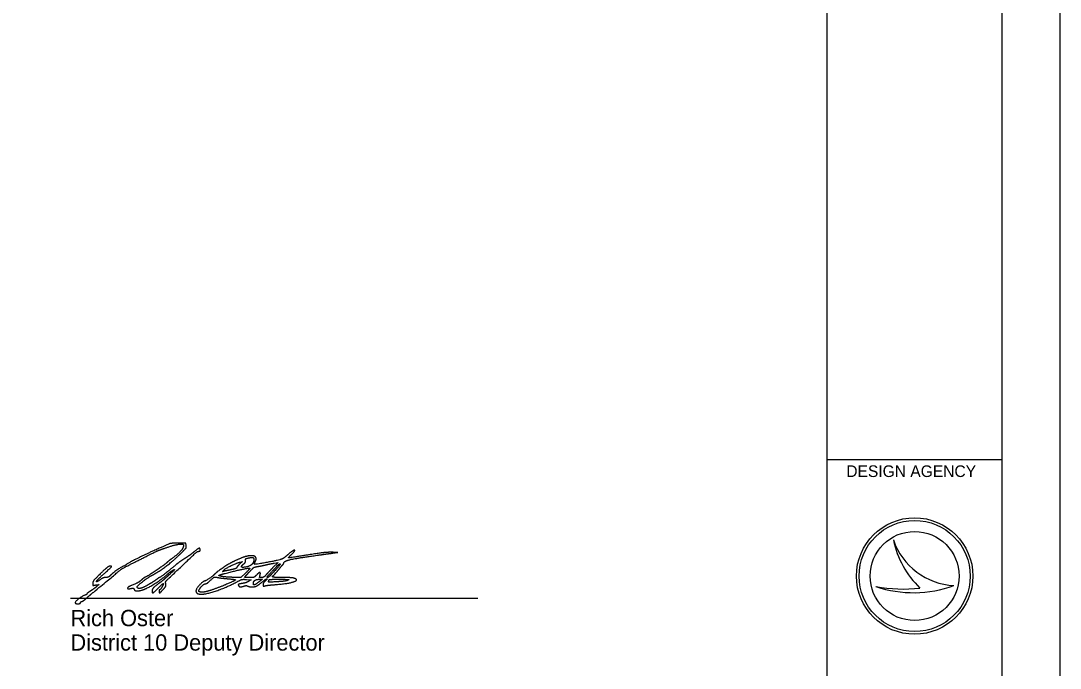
# Model space of a CAD drawing. Extents: x -22 to 431, y -18 to 160.
# Drawn here: x 25.07 to 34, y 2.71 to 8.27 of the extents above; entities that cross this region are included whole.
import ezdxf

# ---------------------------------------------------------------- set-up
doc = ezdxf.new("R2010")
doc.units = 0
for name, color, linetype in [('GM_X_County', 7, 'Continuous'), ('GM_X_Minor_Lake', 7, 'Continuous'), ('GM_X_Section', 7, 'Continuous'), ('GM_X_Township', 7, 'Continuous')]:
    doc.layers.add(name, color=color, linetype=linetype)

msp = doc.modelspace()

# ---------------------------------------------------------------- linework, layer by layer
at = {"layer": 'GM_X_County'}
msp.add_lwpolyline([(0, 0), (34, 0), (34, 22), (0, 22)], close=True, dxfattribs=at)
at = {"layer": 'GM_X_Minor_Lake'}
msp.add_line((25.5414, 3.2723), (25.5414, 3.2723), dxfattribs=at)
for points in [[(26.4927, 3.7616), (26.4902, 3.7834), (26.4302, 3.7827)], [(27.7539, 3.6969), (27.7952, 3.7027), (27.7575, 3.7037)], [(26.9553, 3.6188), (26.9777, 3.6241), (26.9533, 3.6018)], [(27.2502, 3.6103), (27.2828, 3.615), (27.239, 3.5717)], [(27.0037, 3.5251), (26.9645, 3.4871), (26.9111, 3.4881)], [(27.0364, 3.4871), (26.9955, 3.4871), (27.0347, 3.5317)], [(25.7195, 3.4229), (25.7477, 3.4279), (25.7252, 3.409)], [(27.013, 3.4707), (27.0522, 3.4684), (27.0308, 3.4544)], [(27.124, 3.4721), (27.1491, 3.4721), (27.1196, 3.4498)]]:
    msp.add_lwpolyline(points, dxfattribs=at)
for points in [[(26.4302, 3.7827), (26.3677, 3.782), (26.3413, 3.7738), (26.2052, 3.7126)], [(26.3327, 3.7466), (26.3967, 3.7685), (26.4714, 3.7785), (26.4714, 3.7652)], [(26.4714, 3.7652), (26.4714, 3.7413), (26.4264, 3.6899), (26.3672, 3.6464)], [(26.4326, 3.6791), (26.4866, 3.7314), (26.4948, 3.7427), (26.4927, 3.7616)], [(26.2052, 3.7126), (26.125, 3.6766), (25.9891, 3.607), (25.9758, 3.5952)], [(26.1227, 3.6544), (26.2348, 3.7107), (26.2605, 3.722), (26.3327, 3.7466)], [(26.2093, 3.5112), (26.263, 3.5396), (26.3777, 3.6258), (26.4326, 3.6791)], [(26.3476, 3.483), (26.569, 3.6926), (26.5909, 3.7121), (26.6045, 3.7121)], [(26.5646, 3.7097), (26.5484, 3.696), (26.5115, 3.6695), (26.4827, 3.6509)], [(26.6139, 3.7234), (26.6139, 3.7414), (26.5963, 3.7365), (26.5646, 3.7097)], [(26.6045, 3.7121), (26.6097, 3.7121), (26.6139, 3.7172), (26.6139, 3.7234)], [(27.0565, 3.6746), (27.029, 3.6746), (26.9672, 3.6555), (26.9117, 3.6298)], [(27.0866, 3.6224), (27.0994, 3.6463), (27.0831, 3.6746), (27.0565, 3.6746)], [(27.3651, 3.6813), (27.3459, 3.6644), (27.3234, 3.648), (27.3152, 3.645)], [(27.3339, 3.6143), (27.3339, 3.6287), (27.4565, 3.6559), (27.6272, 3.6793)], [(27.4007, 3.6878), (27.4375, 3.7246), (27.408, 3.7193), (27.3651, 3.6813)], [(27.4974, 3.6738), (27.3771, 3.6543), (27.3685, 3.6555), (27.4007, 3.6878)], [(27.7575, 3.7037), (27.7131, 3.7048), (27.6291, 3.6952), (27.4974, 3.6738)], [(27.6272, 3.6793), (27.6742, 3.6858), (27.7312, 3.6937), (27.7539, 3.6969)], [(25.7139, 3.3742), (25.9385, 3.5602), (25.9481, 3.5667), (26.1227, 3.6544)], [(25.8343, 3.5833), (25.8262, 3.582), (25.7908, 3.5526), (25.7555, 3.518)], [(25.8245, 3.5517), (25.8523, 3.5759), (25.8556, 3.5868), (25.8343, 3.5833)], [(25.9567, 3.5846), (25.948, 3.5846), (25.8583, 3.5208), (25.8392, 3.501)], [(25.9758, 3.5952), (25.9693, 3.5894), (25.9607, 3.5846), (25.9567, 3.5846)], [(26.3269, 3.6133), (26.3121, 3.5984), (26.1454, 3.4871), (26.138, 3.4871)], [(26.4077, 3.5977), (26.363, 3.5593), (26.2703, 3.4871), (26.2656, 3.4871)], [(26.3672, 3.6464), (26.3523, 3.6354), (26.3342, 3.6205), (26.3269, 3.6133)], [(26.4827, 3.6509), (26.4538, 3.6323), (26.42, 3.6083), (26.4077, 3.5977)], [(26.9117, 3.6298), (26.8697, 3.6103), (26.7612, 3.538), (26.7355, 3.5123)], [(26.8164, 3.5494), (26.8308, 3.5643), (26.9259, 3.6118), (26.9553, 3.6188)], [(26.9289, 3.572), (26.9289, 3.5679), (26.9095, 3.5603), (26.8858, 3.5552)], [(26.9533, 3.6018), (26.9399, 3.5896), (26.9289, 3.5762), (26.9289, 3.572)], [(27.0583, 3.6002), (27.0419, 3.5829), (26.9609, 3.5695), (26.9706, 3.5857)], [(26.9706, 3.5857), (26.974, 3.5913), (26.9829, 3.6003), (26.9903, 3.6057)], [(26.9903, 3.6057), (26.9978, 3.6111), (27.0039, 3.6233), (27.0039, 3.6329)], [(27.0039, 3.6329), (27.0039, 3.6463), (27.0092, 3.6513), (27.0273, 3.655)], [(27.0273, 3.655), (27.0402, 3.6575), (27.0554, 3.6596), (27.0611, 3.6596)], [(27.0347, 3.5317), (27.0671, 3.5685), (27.0793, 3.5771), (27.1046, 3.5811)], [(27.0611, 3.6596), (27.0761, 3.6596), (27.0741, 3.6169), (27.0583, 3.6002)], [(27.0818, 3.6017), (27.0796, 3.604), (27.0817, 3.6133), (27.0866, 3.6224)], [(27.3152, 3.645), (27.2878, 3.6349), (27.0861, 3.5975), (27.0818, 3.6017)], [(27.1046, 3.5811), (27.1214, 3.5837), (27.1537, 3.5903), (27.1764, 3.5957)], [(27.1764, 3.5957), (27.1991, 3.6012), (27.2323, 3.6077), (27.2502, 3.6103)], [(27.239, 3.5717), (27.2149, 3.5478), (27.1876, 3.519), (27.1783, 3.5077)], [(27.1918, 3.4871), (27.1839, 3.4871), (27.2053, 3.5123), (27.2763, 3.5866)], [(27.3009, 3.6052), (27.3044, 3.6017), (27.2806, 3.5727), (27.2279, 3.5163)], [(27.2763, 3.5866), (27.2879, 3.5987), (27.299, 3.6071), (27.3009, 3.6052)], [(27.2814, 3.5471), (27.2999, 3.5698), (27.3193, 3.5928), (27.3245, 3.5983)], [(27.3245, 3.5983), (27.3297, 3.6037), (27.3339, 3.6109), (27.3339, 3.6143)], [(25.7555, 3.518), (25.7091, 3.4726), (25.6914, 3.45), (25.6914, 3.4366)], [(25.7245, 3.4515), (25.7208, 3.4552), (25.7677, 3.5022), (25.8245, 3.5517)], [(25.8031, 3.4871), (25.7901, 3.4871), (25.7693, 3.4787), (25.7545, 3.4673)], [(25.8392, 3.501), (25.8319, 3.4934), (25.8156, 3.4871), (25.8031, 3.4871)], [(26.0739, 3.4072), (26.0739, 3.4167), (26.1697, 3.4903), (26.2093, 3.5112)], [(26.138, 3.4871), (26.1354, 3.4871), (26.1242, 3.4787), (26.113, 3.4684)], [(26.1272, 3.3834), (26.1642, 3.3962), (26.2908, 3.4772), (26.3364, 3.5174)], [(26.2656, 3.4871), (26.2629, 3.4871), (26.2567, 3.4837), (26.2517, 3.4795)], [(26.3523, 3.5139), (26.3377, 3.5012), (26.3201, 3.4854), (26.3132, 3.4787)], [(26.3191, 3.4334), (26.3162, 3.4487), (26.322, 3.4587), (26.3476, 3.483)], [(26.3364, 3.5174), (26.3508, 3.5301), (26.369, 3.544), (26.3767, 3.5483)], [(26.3767, 3.5483), (26.3975, 3.5599), (26.3849, 3.5421), (26.3523, 3.5139)], [(26.7355, 3.5123), (26.7202, 3.497), (26.6609, 3.4571), (26.6534, 3.4571)], [(26.6856, 3.4479), (26.7298, 3.4881), (26.7407, 3.4932), (26.7695, 3.487)], [(26.7695, 3.487), (26.785, 3.4837), (26.8258, 3.4786), (26.8602, 3.4757)], [(26.7743, 3.5042), (26.7724, 3.5062), (26.797, 3.5146), (26.8292, 3.5228)], [(26.9111, 3.4881), (26.8558, 3.489), (26.7806, 3.4979), (26.7743, 3.5042)], [(26.8239, 3.5418), (26.8071, 3.5382), (26.8063, 3.539), (26.8164, 3.5494)], [(26.8858, 3.5552), (26.8621, 3.5501), (26.8342, 3.544), (26.8239, 3.5418)], [(26.8292, 3.5228), (26.926, 3.5476), (27.0355, 3.5705), (27.0393, 3.5667)], [(27.0393, 3.5667), (27.0413, 3.5647), (27.0253, 3.546), (27.0037, 3.5251)], [(27.095, 3.5058), (27.0804, 3.4904), (27.0702, 3.4871), (27.0364, 3.4871)], [(27.1283, 3.5059), (27.1345, 3.5306), (27.1185, 3.5306), (27.095, 3.5058)], [(27.1426, 3.4871), (27.1261, 3.4871), (27.1242, 3.4896), (27.1283, 3.5059)], [(27.1783, 3.5077), (27.1681, 3.4952), (27.1541, 3.4871), (27.1426, 3.4871)], [(27.2279, 3.5163), (27.2129, 3.5003), (27.1967, 3.4871), (27.1918, 3.4871)], [(27.2364, 3.494), (27.2364, 3.4978), (27.2389, 3.502), (27.242, 3.5034)], [(27.317, 3.487), (27.2727, 3.4871), (27.2364, 3.4902), (27.2364, 3.494)], [(27.242, 3.5034), (27.2451, 3.5048), (27.2628, 3.5245), (27.2814, 3.5471)], [(27.2664, 3.4268), (27.3777, 3.4354), (27.4663, 3.4685), (27.4148, 3.4823)], [(27.4148, 3.4823), (27.4054, 3.4849), (27.3614, 3.487), (27.317, 3.487)], [(25.7252, 3.409), (25.7128, 3.3987), (25.6883, 3.381), (25.6708, 3.3697)], [(25.6914, 3.4366), (25.6914, 3.4192), (25.6933, 3.4183), (25.7195, 3.4229)], [(25.7545, 3.4673), (25.7402, 3.4565), (25.7267, 3.4493), (25.7245, 3.4515)], [(26.0233, 3.4188), (25.992, 3.4056), (25.9899, 3.3865), (26.0205, 3.3932)], [(26.0205, 3.3932), (26.0361, 3.3966), (26.0432, 3.3947), (26.0465, 3.3863)], [(26.113, 3.4684), (26.0938, 3.4506), (26.0794, 3.4426), (26.0233, 3.4188)], [(26.1525, 3.4162), (26.1154, 3.3955), (26.0739, 3.3907), (26.0739, 3.4072)], [(26.2517, 3.4795), (26.2371, 3.4672), (26.1893, 3.4367), (26.1525, 3.4162)], [(26.2588, 3.4355), (26.2189, 3.406), (26.2014, 3.3853), (26.2014, 3.3676)], [(26.2014, 3.3676), (26.2014, 3.3515), (26.2189, 3.3605), (26.2513, 3.3934)], [(26.2513, 3.3934), (26.2897, 3.4323), (26.3038, 3.437), (26.2854, 3.4047)], [(26.3132, 3.4787), (26.3064, 3.4719), (26.2819, 3.4525), (26.2588, 3.4355)], [(26.2854, 3.4047), (26.2784, 3.3923), (26.2701, 3.3822), (26.267, 3.3822)], [(26.2988, 3.3869), (26.3165, 3.407), (26.3218, 3.4193), (26.3191, 3.4334)], [(26.6534, 3.4571), (26.6425, 3.4571), (26.5854, 3.3987), (26.5801, 3.3821)], [(26.6074, 3.3846), (26.6171, 3.4034), (26.6514, 3.434), (26.6631, 3.4344)], [(26.6245, 3.3446), (26.6741, 3.3446), (26.8334, 3.3997), (26.9307, 3.4505)], [(26.6631, 3.4344), (26.6675, 3.4345), (26.6776, 3.4406), (26.6856, 3.4479)], [(26.9164, 3.4651), (26.907, 3.457), (26.805, 3.4132), (26.7414, 3.3898)], [(26.8602, 3.4757), (26.8946, 3.4728), (26.9199, 3.468), (26.9164, 3.4651)], [(26.9307, 3.4505), (26.9656, 3.4687), (26.9812, 3.4725), (27.013, 3.4707)], [(26.9802, 3.4365), (26.9487, 3.4323), (26.9377, 3.4229), (26.9499, 3.4107)], [(26.9499, 3.4107), (26.9551, 3.4055), (26.9661, 3.4058), (26.9843, 3.4119)], [(27.0308, 3.4544), (27.019, 3.4467), (26.9962, 3.4387), (26.9802, 3.4365)], [(26.9843, 3.4119), (26.9991, 3.4167), (27.015, 3.4183), (27.0198, 3.4154)], [(27.0198, 3.4154), (27.0338, 3.4067), (27.0815, 3.4059), (27.0977, 3.414)], [(27.0714, 3.4372), (27.0714, 3.4546), (27.0978, 3.4721), (27.124, 3.4721)], [(27.1196, 3.4498), (27.0876, 3.4256), (27.0714, 3.4214), (27.0714, 3.4372)], [(27.0977, 3.414), (27.1059, 3.4182), (27.1272, 3.4334), (27.1449, 3.4477)], [(27.1449, 3.4477), (27.1775, 3.4741), (27.1968, 3.4787), (27.169, 3.4534)], [(27.169, 3.4534), (27.1607, 3.4459), (27.1539, 3.4332), (27.1539, 3.4251)], [(27.1539, 3.4251), (27.1539, 3.4133), (27.1573, 3.4114), (27.1708, 3.4156)], [(27.1708, 3.4156), (27.1801, 3.4184), (27.2231, 3.4235), (27.2664, 3.4268)], [(27.2767, 3.4506), (27.2131, 3.4466), (27.1994, 3.4476), (27.2026, 3.4558)], [(27.2026, 3.4558), (27.2047, 3.4613), (27.2064, 3.4673), (27.2064, 3.469)], [(27.2064, 3.469), (27.2064, 3.4707), (27.2461, 3.472), (27.2945, 3.4719)], [(27.3687, 3.4635), (27.3609, 3.4591), (27.3196, 3.4532), (27.2767, 3.4506)], [(27.2945, 3.4719), (27.3616, 3.4717), (27.3793, 3.4697), (27.3687, 3.4635)], [(25.6313, 3.3371), (25.6171, 3.3371), (25.5414, 3.2826), (25.5414, 3.2723)], [(25.5995, 3.2825), (25.6068, 3.2852), (25.6211, 3.295), (25.6314, 3.3044)], [(25.6389, 3.3431), (25.6389, 3.3398), (25.6355, 3.3371), (25.6313, 3.3371)], [(25.6314, 3.3044), (25.6417, 3.3137), (25.6788, 3.3451), (25.7139, 3.3742)], [(25.6708, 3.3697), (25.6533, 3.3584), (25.6389, 3.3464), (25.6389, 3.3431)], [(26.0465, 3.3863), (26.0519, 3.3722), (26.0907, 3.3708), (26.1272, 3.3834)], [(26.2614, 3.3709), (26.2614, 3.3527), (26.2732, 3.3578), (26.2988, 3.3869)], [(26.267, 3.3822), (26.2639, 3.3822), (26.2614, 3.3771), (26.2614, 3.3709)], [(26.5801, 3.3821), (26.5774, 3.3735), (26.5792, 3.3615), (26.5842, 3.3555)], [(26.5842, 3.3555), (26.5895, 3.3492), (26.6063, 3.3446), (26.6245, 3.3446)], [(26.6083, 3.3645), (26.6013, 3.3674), (26.601, 3.3722), (26.6074, 3.3846)], [(26.7414, 3.3898), (26.6841, 3.3688), (26.6251, 3.3576), (26.6083, 3.3645)], [(25.5414, 3.2723), (25.5414, 3.266), (25.55, 3.2621), (25.5639, 3.2621)], [(25.5639, 3.2621), (25.5763, 3.2621), (25.5864, 3.2656), (25.5864, 3.2699)], [(25.5864, 3.2699), (25.5864, 3.2741), (25.5923, 3.2798), (25.5995, 3.2825)]]:
    msp.add_open_spline(points, degree=2, dxfattribs=at)
at = {"layer": 'GM_X_Section'}
for p, q in [((32.5675, 3.8096), (32.5675, 3.8096)), ((32.75, 3.5), (32.75, 3.5)), ((32.4172, 3.4095), (32.4172, 3.4095)), ((33.0873, 3.4185), (33.0873, 3.4185)), ((25.5, 3.3094), (29, 3.3094))]:
    msp.add_line(p, q, dxfattribs=at)
for radius in [0.5, 0.4768, 0.4768, 0.3822]:
    msp.add_circle((32.75, 3.5), radius, dxfattribs=at)
for centre, radius, start, end in [((33.116, 3.9976), 0.5798, 198.92567, 198.93195), ((33.3467, 3.9701), 0.7956, 191.63793, 191.64215), ((33.116, 3.9976), 0.5798, 198.93195, 267.16574), ((33.3467, 3.9701), 0.7956, 191.64215, 226.09467), ((32.648, 4.6544), 1.2661, 259.49639, 259.49952), ((32.7394, 4.37), 1.0131, 251.45274, 251.45764), ((32.7394, 4.37), 1.0131, 251.45764, 290.08324), ((32.648, 4.6544), 1.2661, 259.49952, 276.66723)]:
    msp.add_arc(centre, radius, start, end, dxfattribs=at)
at = {"layer": 'GM_X_Township'}
for p, q in [((32, 0.5), (32, 21.5)), ((32, 4.5), (33.5, 4.5))]:
    msp.add_line(p, q, dxfattribs=at)
msp.add_lwpolyline([(1.5, 21.5), (33.5, 21.5), (33.5, 0.5), (1.5, 0.5)], close=True, dxfattribs=at)

# ---------------------------------------------------------------- texts
at = {"layer": 'GM_X_Minor_Lake'}
for s, p in [('Rich Oster', (25.5, 3.0694)), ('District 10 Deputy Director', (25.5, 2.8594))]:
    msp.add_text(s, height=0.14, dxfattribs=at).set_placement(p)
at = {"layer": 'GM_X_Section'}
msp.add_text('DESIGN AGENCY', height=0.1, dxfattribs=at).set_placement((32.1629, 4.35))

doc.saveas('drawing.dxf')
